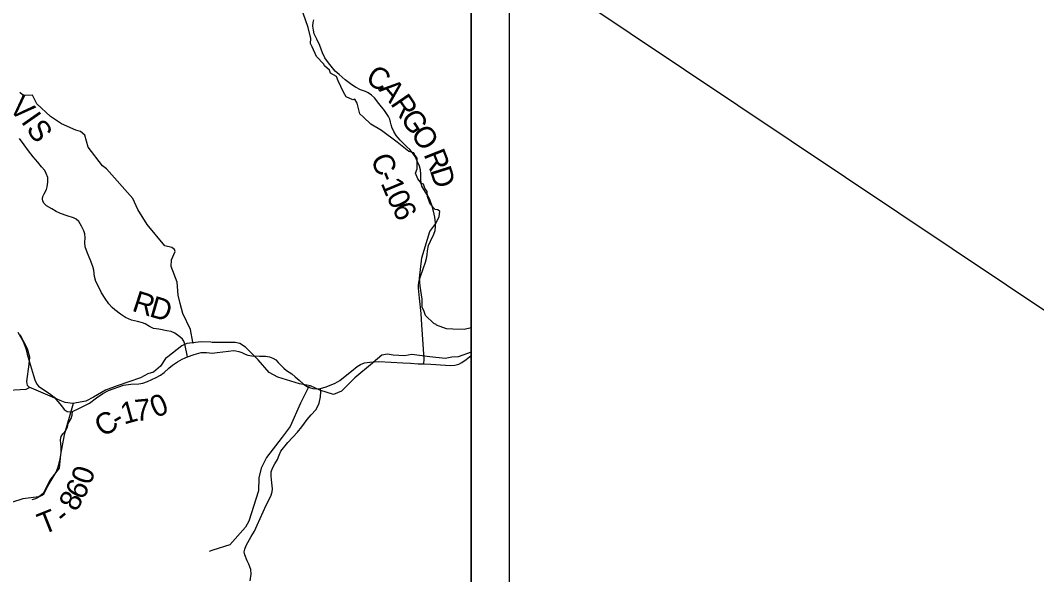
# Model space of a CAD drawing. Extents: x -1.8 to 75.7, y -2 to 25.
# Drawn here: x 7.704 to 10.399, y 15.46 to 16.93 of the extents above; entities that cross this region are included whole.
import ezdxf

# ---------------------------------------------------------------- set-up
doc = ezdxf.new("R2010")
doc.units = 0
for name, color, linetype in [('GM_X_County_Road', 7, 'Continuous'), ('GM_X_County_Road_Text', 7, 'Continuous'), ('GM_X_Minor_River', 7, 'Continuous'), ('GM_X_Township', 7, 'Continuous'), ('GM_X_Township_Road', 7, 'Continuous'), ('GM_X_Township_Road_Text', 7, 'Continuous'), ('SH_Data', 7, 'Continuous'), ('TX_P_1', 7, 'Continuous')]:
    doc.layers.add(name, color=color, linetype=linetype)

msp = doc.modelspace()

# ---------------------------------------------------------------- linework, layer by layer
at = {"layer": 'GM_X_County_Road'}
for points in [[(8.6067, 16.7458), (8.6065, 16.7458), (8.593, 16.7525), (8.583, 16.7584), (8.5654, 16.7717), (8.5496, 16.7857), (8.5388, 16.7953), (8.5211, 16.817), (8.5117, 16.8304), (8.5056, 16.8437), (8.4989, 16.863), (8.4902, 16.8798), (8.4836, 16.8938), (8.4816, 16.9033), (8.4801, 16.9141), (8.4805, 16.9239), (8.483, 16.9311)], [(8.6919, 16.641), (8.6905, 16.6438), (8.6877, 16.6529), (8.6859, 16.6599), (8.6842, 16.668), (8.6809, 16.6747), (8.6772, 16.6799), (8.6698, 16.6906), (8.6549, 16.7092), (8.6432, 16.7238), (8.6353, 16.7312), (8.6266, 16.7375), (8.6198, 16.7407), (8.6067, 16.7458)], [(8.7742, 16.0188), (8.7749, 16.031), (8.7724, 16.0711), (8.7689, 16.1223), (8.767, 16.152), (8.7628, 16.1934), (8.7607, 16.2106), (8.7598, 16.2198), (8.76, 16.2263), (8.7613, 16.2356), (8.7642, 16.2481), (8.7724, 16.2712), (8.779, 16.2884), (8.7814, 16.2982), (8.7827, 16.3082), (8.7838, 16.3187), (8.7866, 16.3324), (8.7916, 16.3446), (8.8006, 16.3625), (8.804, 16.3725), (8.8054, 16.3828), (8.8054, 16.3926), (8.8036, 16.4079), (8.8001, 16.4234), (8.7962, 16.4366), (8.7908, 16.4524), (8.7864, 16.4621), (8.774, 16.4809), (8.7692, 16.4901), (8.7668, 16.4979), (8.7664, 16.5081), (8.7666, 16.5219), (8.7652, 16.5332), (8.7626, 16.543), (8.7578, 16.5548), (8.7511, 16.5683), (8.7435, 16.5797), (8.7375, 16.587), (8.7291, 16.5945), (8.7112, 16.6121), (8.701, 16.6241), (8.6946, 16.6352), (8.6919, 16.641)], [(8.1476, 16.0376), (8.1449, 16.0511), (8.141, 16.0714), (8.1383, 16.079), (8.1341, 16.0847), (8.1272, 16.0906), (8.1137, 16.1001), (8.1039, 16.1048), (8.0929, 16.1068), (8.0715, 16.1107), (8.0575, 16.1129), (8.0467, 16.1176), (8.0352, 16.1247), (8.0281, 16.1274), (8.0151, 16.1308), (7.9994, 16.135), (7.9836, 16.1414), (7.9701, 16.1505), (7.9547, 16.1618), (7.9476, 16.1684), (7.939, 16.1782), (7.9296, 16.1919), (7.9196, 16.2072), (7.9122, 16.2221), (7.9046, 16.2376), (7.9012, 16.2501), (7.899, 16.267), (7.8963, 16.2769), (7.8896, 16.2953), (7.8823, 16.3127), (7.8766, 16.3291), (7.8757, 16.3404), (7.8764, 16.3532), (7.8752, 16.3635), (7.8727, 16.3718), (7.8666, 16.3841), (7.8599, 16.3961), (7.8528, 16.4025), (7.8455, 16.4062), (7.8288, 16.4116), (7.8109, 16.4177), (7.7996, 16.4231), (7.7878, 16.4298), (7.7738, 16.4381), (7.7677, 16.4443), (7.764, 16.4506), (7.763, 16.4565), (7.7637, 16.4622), (7.7672, 16.4698), (7.7738, 16.4811), (7.7758, 16.4884), (7.7775, 16.5007), (7.777, 16.5127), (7.7733, 16.524), (7.7695, 16.5312), (7.7608, 16.5412), (7.7507, 16.5537), (7.7389, 16.5675), (7.7259, 16.5837), (7.7142, 16.5994), (7.7026, 16.6165)], [(7.6977, 16.1031), (7.7119, 16.0781), (7.7166, 16.067), (7.7186, 16.06), (7.7225, 16.0442), (7.7291, 16.023), (7.7392, 15.9877), (7.7426, 15.9762), (7.748, 15.9649), (7.7527, 15.9598), (7.7645, 15.9521), (7.7819, 15.9406), (7.7939, 15.9303), (7.8035, 15.9195), (7.8133, 15.9072), (7.8209, 15.8977), (7.8283, 15.8927), (7.8352, 15.8915), (7.8428, 15.8925), (7.8595, 15.9004), (7.8882, 15.9151), (7.9066, 15.9291), (7.923, 15.9406), (7.9385, 15.9485), (7.9778, 15.962), (7.9974, 15.9654), (8.0183, 15.9661), (8.0293, 15.9676), (8.0418, 15.9723), (8.0646, 15.9826), (8.0762, 15.9885), (8.086, 15.9956), (8.0985, 16.0076), (8.1083, 16.0157), (8.1208, 16.0241), (8.1336, 16.0312), (8.1412, 16.0349), (8.1476, 16.0376), (8.1653, 16.0439), (8.1837, 16.0491), (8.1977, 16.0493), (8.2136, 16.0474), (8.2266, 16.0486), (8.2561, 16.0528), (8.2698, 16.0542), (8.276, 16.0538), (8.2833, 16.0518), (8.2917, 16.0488), (8.3005, 16.0447), (8.3079, 16.0422), (8.3184, 16.0403), (8.3382, 16.0395), (8.3543, 16.039), (8.3652, 16.0375), (8.3737, 16.0344), (8.3816, 16.0296), (8.3883, 16.0225), (8.3975, 16.0126), (8.4027, 16.0076), (8.4103, 16.0015), (8.4243, 15.9922), (8.4333, 15.9847), (8.4437, 15.9754), (8.4544, 15.966), (8.4662, 15.9577), (8.4736, 15.9551), (8.4795, 15.9534), (8.4901, 15.9525), (8.5003, 15.9539), (8.515, 15.9584), (8.5394, 15.968), (8.5516, 15.9752), (8.566, 15.986), (8.5824, 15.9996), (8.5972, 16.0115), (8.6061, 16.0175), (8.617, 16.0214), (8.631, 16.0236), (8.655, 16.0248), (8.6876, 16.0233), (8.7188, 16.0212), (8.7386, 16.0203), (8.7592, 16.0192), (8.7742, 16.0188), (8.7926, 16.0178), (8.8312, 16.0157), (8.8456, 16.0147), (8.8566, 16.0155), (8.8667, 16.0182), (8.8747, 16.0221), (8.8861, 16.0302), (8.9, 16.0407)], [(8.3134, 15.444), (8.3162, 15.4613), (8.3153, 15.4736), (8.3105, 15.4874), (8.3059, 15.4968), (8.2995, 15.5124), (8.2982, 15.5203), (8.2995, 15.528), (8.3028, 15.5375), (8.3162, 15.5614), (8.3252, 15.5754), (8.3327, 15.5914), (8.3559, 15.6439), (8.3682, 15.6685), (8.3717, 15.6799), (8.3726, 15.6875), (8.3715, 15.7033), (8.3693, 15.7207), (8.3695, 15.733), (8.3726, 15.7426), (8.379, 15.7534), (8.3864, 15.765), (8.3906, 15.7764), (8.3952, 15.7878), (8.4137, 15.81), (8.4389, 15.8379), (8.4505, 15.8523), (8.4646, 15.8714), (8.4753, 15.8839), (8.4876, 15.8967), (8.4924, 15.905), (8.4964, 15.9144), (8.5003, 15.9315), (8.5008, 15.9443), (8.5003, 15.9539)]]:
    msp.add_lwpolyline(points, dxfattribs=at)
at = {"layer": 'GM_X_Minor_River'}
for points in [[(8.9, 16.1142), (8.8807, 16.1098), (8.8512, 16.1108), (8.8342, 16.1115), (8.8081, 16.1217), (8.8073, 16.1236), (8.8005, 16.1263), (8.7789, 16.1468), (8.7748, 16.1574), (8.7695, 16.1692), (8.7698, 16.1901), (8.7641, 16.225), (8.7626, 16.2459), (8.769, 16.3003), (8.7904, 16.3695), (8.8063, 16.3908), (8.815, 16.4095), (8.8165, 16.4224), (8.8112, 16.4273), (8.8044, 16.4285), (8.7919, 16.4414), (8.7904, 16.4451), (8.7839, 16.4622), (8.7832, 16.4759), (8.7771, 16.4846), (8.7733, 16.4953), (8.7676, 16.4975), (8.7586, 16.5093), (8.7521, 16.5245), (8.7563, 16.5363), (8.7562, 16.5644), (8.7498, 16.5743), (8.7475, 16.5785), (8.7347, 16.5815), (8.7082, 16.6031), (8.7037, 16.6069), (8.6617, 16.6375), (8.6333, 16.6546), (8.614, 16.6732), (8.6045, 16.6819), (8.5973, 16.7104), (8.5917, 16.721), (8.5864, 16.7187), (8.5686, 16.7267), (8.5614, 16.7396), (8.5474, 16.7696), (8.5425, 16.7806), (8.5269, 16.79), (8.5239, 16.7972), (8.5107, 16.8094), (8.5088, 16.8132), (8.4899, 16.834), (8.4785, 16.8595), (8.4736, 16.8682), (8.4747, 16.8811), (8.4675, 16.9108), (8.4546, 16.9484)], [(8.1632, 16.0731), (8.1616, 16.0768), (8.1555, 16.11), (8.1352, 16.1528), (8.1284, 16.1789), (8.1231, 16.2011), (8.12, 16.2353), (8.1046, 16.2772), (8.1051, 16.2947), (8.1145, 16.3164), (8.1135, 16.3221), (8.1057, 16.3273), (8.0873, 16.3317), (8.0403, 16.3886), (8.0158, 16.4281), (8.0023, 16.4574), (7.9325, 16.5364), (7.9222, 16.5443), (7.8847, 16.5937), (7.8755, 16.6251), (7.8641, 16.6346), (7.8517, 16.6384), (7.8137, 16.6552), (7.7848, 16.6744), (7.7484, 16.7082), (7.7366, 16.7317), (7.7184, 16.73), (7.7105, 16.7318), (7.7028, 16.7385)], [(8.9, 16.0495), (8.8656, 16.0379), (8.8482, 16.0363), (8.8305, 16.0329), (8.79, 16.0373), (8.7424, 16.0433), (8.7227, 16.0406), (8.6928, 16.042), (8.6781, 16.045), (8.6626, 16.042), (8.6403, 16.0222), (8.6381, 16.0206), (8.5916, 15.9821), (8.5557, 15.9467), (8.5349, 15.9379), (8.4983, 15.9489), (8.4733, 15.9602), (8.4449, 15.9655), (8.3871, 15.9832), (8.3644, 15.9957), (8.3352, 16.0294), (8.3016, 16.0632), (8.2861, 16.0726), (8.2736, 16.0757), (8.2131, 16.0755), (8.2097, 16.0763), (8.184, 16.0777), (8.1462, 16.0731), (8.1326, 16.067), (8.0956, 16.0376), (8.0892, 16.0334), (8.0759, 16.0129), (8.0571, 15.9965), (8.0423, 15.9923), (8.0234, 15.982), (7.9611, 15.9602), (7.9305, 15.9487), (7.8987, 15.9304), (7.8783, 15.9204), (7.8432, 15.9135), (7.8231, 15.9161), (7.8103, 15.9214), (7.8023, 15.9256), (7.7275, 15.957), (7.7237, 15.9611), (7.7214, 15.9725), (7.7278, 16.0178), (7.7293, 16.0368), (7.7232, 16.0584), (7.7043, 16.096)], [(7.7295, 15.9561), (7.7186, 15.9508), (7.6583, 15.9478), (7.5988, 15.933), (7.5763, 15.9236), (7.5638, 15.9142), (7.5337, 15.8824), (7.5035, 15.8492), (7.4829, 15.8197), (7.4564, 15.7617), (7.4124, 15.6875), (7.3918, 15.6602), (7.3842, 15.6474), (7.3889, 15.6184)], [(8.4698, 15.9608), (8.4474, 15.9147), (8.4194, 15.8529), (8.3982, 15.8247), (8.3568, 15.7706), (8.3428, 15.7426), (8.3367, 15.7166), (8.3356, 15.6824), (8.3105, 15.6016), (8.3017, 15.5855), (8.2598, 15.5387), (8.2144, 15.5249), (8.2053, 15.5218)], [(7.8443, 15.9137), (7.8208, 15.8303), (7.8113, 15.7785), (7.8075, 15.7422), (7.7831, 15.7103), (7.765, 15.6748), (7.7531, 15.6665), (7.7109, 15.6614), (7.6812, 15.6517), (7.6596, 15.6372), (7.6088, 15.5705), (7.6037, 15.5528), (7.6024, 15.524), (7.601, 15.5001)]]:
    msp.add_lwpolyline(points, dxfattribs=at)
at = {"layer": 'GM_X_Township'}
msp.add_lwpolyline([(6.0631, 14.1), (8.9, 14.1), (8.9, 17.0276)], dxfattribs=at)
at = {"layer": 'GM_X_Township_Road'}
msp.add_lwpolyline([(7.7358, 15.6593), (7.7458, 15.6623), (7.7627, 15.6706), (7.7677, 15.675), (7.7716, 15.6834), (7.777, 15.6944), (7.7834, 15.7052), (7.7991, 15.732), (7.8045, 15.746), (7.8104, 15.7659), (7.8126, 15.7838), (7.8128, 15.798), (7.8118, 15.8068), (7.8113, 15.8176), (7.8131, 15.8262), (7.817, 15.8336), (7.8248, 15.8422), (7.8293, 15.8513), (7.8317, 15.8606), (7.8388, 15.8743), (7.842, 15.8827), (7.8428, 15.8925)], dxfattribs=at)
at = {"layer": 'SH_Data'}
for p, q in [((9, 21), (9, 14)), ((8.9, 20.9), (8.9, 14.1))]:
    msp.add_line(p, q, dxfattribs=at)
at = {"layer": 'TX_P_1'}
msp.add_line((-1.8436, 24.3711), (37.5745, -2.0199), dxfattribs=at)

# ---------------------------------------------------------------- texts
at = {"layer": 'GM_X_County_Road_Text'}
for s, rotation, p in [('C', 329.1581, (8.6164, 16.7665)), ('A', 310.3338, (8.6527, 16.7457)), ('V', 314.687, (7.6713, 16.6947)), ('R', 304.3959, (8.6842, 16.7088)), ('I', 305.0173, (7.7048, 16.6611)), ('G', 303.4335, (8.7104, 16.6705)), ('S', 304.5862, (7.7182, 16.6421)), ('O', 303.194, (8.7379, 16.6289)), ('C', 292.4711, (8.6323, 16.5631)), ('R', 291.5072, (8.7729, 16.5747)), ('-', 292.5162, (8.6502, 16.5199)), ('D', 287.6504, (8.7896, 16.5323)), ('1', 292.6769, (8.6592, 16.4982)), ('0', 295.4696, (8.6739, 16.4632)), ('6', 295.758, (8.6891, 16.4313)), ('R', 342.1118, (7.9979, 16.1602)), ('D', 343.9296, (8.0441, 16.1453)), ('7', 5.6189, (8.0103, 15.8667)), ('0', 22.8253, (8.0631, 15.8747)), ('1', 15.4032, (7.9791, 15.8579)), ('C', 32.0401, (7.9235, 15.8229)), ('-', 30.8138, (7.9627, 15.8475))]:
    msp.add_text(s, height=0.0568, rotation=rotation, dxfattribs=at).set_placement(p)
at = {"layer": 'GM_X_Township_Road_Text'}
for s, rotation, p in [('0', 70.935, (7.8907, 15.6956)), ('6', 61.4261, (7.8698, 15.6554)), ('8', 62.0232, (7.8534, 15.6247)), ('T', 21.8814, (7.7645, 15.5654)), ('-', 39.982, (7.8206, 15.5913))]:
    msp.add_text(s, height=0.0568, rotation=rotation, dxfattribs=at).set_placement(p)

doc.saveas('drawing.dxf')
